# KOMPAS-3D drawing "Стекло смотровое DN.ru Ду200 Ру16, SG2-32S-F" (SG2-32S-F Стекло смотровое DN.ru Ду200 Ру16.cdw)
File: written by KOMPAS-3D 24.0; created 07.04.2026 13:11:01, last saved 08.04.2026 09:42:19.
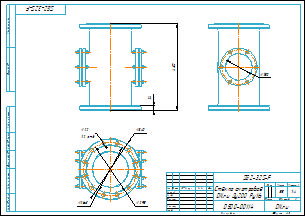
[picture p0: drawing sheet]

Document properties: Автор: Main; Форматы листов документа: A3; Полное имя файла: SG2-32S-F Стекло смотровое DN.ru Ду200 Ру16.m3d; Масса: 55; Наименование: Стекло смотровое DN.ru Ду200 Ру16; Количество листов документа: 1; Примечание: D500-00114

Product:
- Body: Тело 1  | qty 1
    Масса: 65.830714
- Part/product: Стекло смотровое DN.ru Ду200 Ру16  | designation SG2-32S-F
    Масса: 55
    Раздел спецификации: Прочие изделия
    Примечание: D500-00114

Views: Вид 1, Снизу, Проекционный вид 2, Проекционный вид 3
Referenced files in D:\DN.ru Аутсерс\Стекло смотровое DN.ru\Стекло смотровое DN.ru SG2-34G-F тип В ГОСТ 21836-2021 Ду100 Ру16, углеродистая сталь, фланцевое\: SG2-34G-F тип В Стекло смотровое DN.ru Ду100 Ру16.m3d, SG2-34G-F тип ВСтекло смотровое DN.ru Ду100 Ру16.cdw
Referenced files in D:\DN.ru Аутсерс\Стекло смотровое DN.ru\SG2-32S-F Стекло смотровое DN.ru Ду200 Ру16\: SG2-32S-F Стекло смотровое DN.ru Ду200 Ру16.m3d
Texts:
  SG2-32S-F
  Стекло смотровое
  DN.ru Ду200 Ру16
  Стекло смотровое DN.ru Ду200 Ру16
  SG2-32S-F Стекло смотровое DN.ru Ду200 Ру16
Dimensions and other numbers on the sheet: 0; 3; 2; 4; 480; 24; 22; 12 отв.; 340; 295; 268; 150; 1:4; 1; 55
